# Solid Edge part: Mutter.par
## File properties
Dokumentum tartalom típus: 0
Last saved by: psaghy
Revision: 77
Sűrűség: 0,000 kg/m^3
Pontosság: 0,990
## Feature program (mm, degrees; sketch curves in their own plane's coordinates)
base feature "unnamed BaseFeature 1"
sketch for "Furat_1" plane through (7, 0, 0) normal (1, 0, 0) x-axis (0, -1, 0)
hole "Furat_1" through  StartChamferOffset = 0.39 mm; StartChamferAngle = 45 deg
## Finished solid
Body 1: solid body, 23 faces, 47 edges, 26 vertices.
  Faces by surface: cone 14, plane 8, cylinder 1
  Edges by curve: spline 24, circle 16, line 7
Bounding box of the edges (mm): 7.000 x 21.939 x 19.000, from (0, -10.9697, -9.5) to (7, 10.9697, 9.5).
Cylindrical faces by radius (mm): R5.3235 x1
Conical faces (half-angle, radius in mm at the cone's reference point): 45 deg R5.7135 x1, 60 deg R5.6618 x1, 60 deg R10.2348 x12
Planar faces by outward normal: +x 1, +z 1, -x 1, -z 1, oblique 4
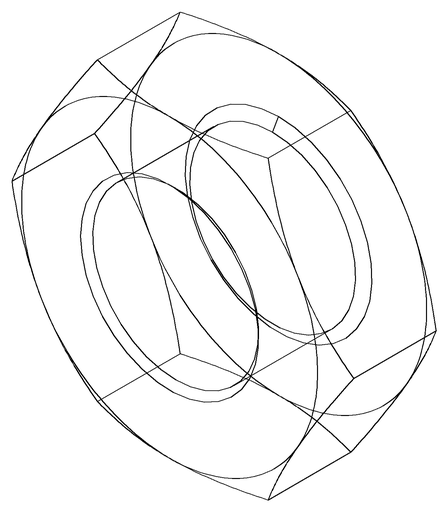
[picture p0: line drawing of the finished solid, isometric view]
